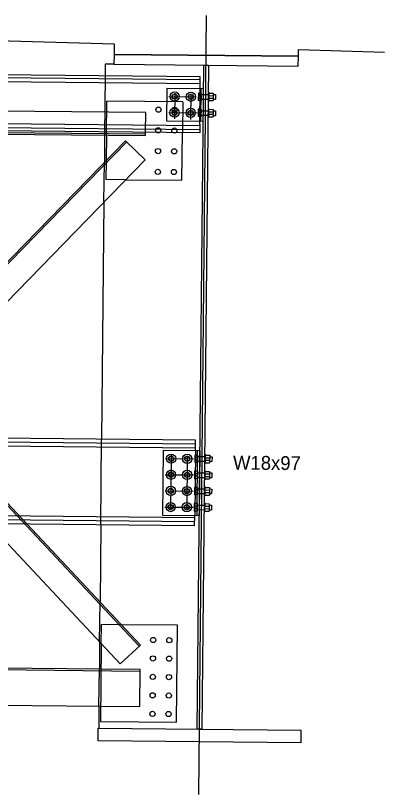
# Model space of a CAD drawing. Extents: x 632312 to 632425, y 378332 to 378413.
# Drawn here: x 632348.57 to 632355.24, y 378382.52 to 378396.59 of the extents above; entities that cross this region are included whole.
import ezdxf

# ---------------------------------------------------------------- set-up
doc = ezdxf.new("R2010")
doc.units = 0
for name, color, linetype in [('B_Boring', 7, 'Continuous'), ('B_Boring Annot', 7, 'Continuous'), ('R_Proposed Const Limits Cut', 7, 'Continuous'), ('R_Shade Removal', 7, 'Continuous'), ('R_Wall', 7, 'Continuous'), ('SHT_Dimensions', 7, 'Continuous')]:
    doc.layers.add(name, color=color, linetype=linetype)

msp = doc.modelspace()

# ---------------------------------------------------------------- linework, layer by layer
at = {"layer": 'B_Boring'}
for p, q in [((632350.191, 378395.714), (632350.189, 378395.499)), ((632350.347, 378395.712), (632350.191, 378395.714)), ((632351.908, 378395.482), (632340.867, 378395.592)), ((632351.907, 378395.432), (632340.866, 378395.541)), ((632351.906, 378395.294), (632351.908, 378395.482)), ((632351.301, 378395.275), (632351.296, 378394.692)), ((632351.968, 378395.269), (632351.301, 378395.275)), ((632351.874, 378395.192), (632351.872, 378395.056)), ((632351.925, 378395.146), (632351.873, 378395.147)), ((632351.926, 378395.191), (632351.874, 378395.192)), ((632351.921, 378394.686), (632351.926, 378395.269)), ((632351.926, 378395.191), (632351.924, 378395.056)), ((632352.051, 378395.206), (632352.049, 378395.039)), ((632352.051, 378395.206), (632352.061, 378395.205)), ((632352.061, 378395.205), (632352.06, 378395.039)), ((632352.061, 378395.19), (632352.144, 378395.189)), ((632352.061, 378395.145), (632352.144, 378395.144)), ((632352.144, 378395.189), (632352.143, 378395.054)), ((632352.144, 378395.163), (632352.186, 378395.163)), ((632352.186, 378395.163), (632352.185, 378395.079)), ((632350.216, 378395.047), (632350.216, 378395.047)), ((632351.924, 378395.056), (632351.872, 378395.056)), ((632351.925, 378395.101), (632351.873, 378395.101)), ((632352.049, 378395.039), (632352.06, 378395.039)), ((632352.06, 378395.1), (632352.144, 378395.099)), ((632352.06, 378395.054), (632352.143, 378395.054)), ((632352.143, 378395.08), (632352.185, 378395.079)), ((632351.871, 378394.9), (632351.869, 378394.765)), ((632351.922, 378394.854), (632351.87, 378394.855)), ((632351.923, 378394.899), (632351.871, 378394.9)), ((632351.923, 378394.899), (632351.921, 378394.764)), ((632352.048, 378394.914), (632352.046, 378394.747)), ((632352.048, 378394.914), (632352.058, 378394.914)), ((632352.058, 378394.914), (632352.057, 378394.747)), ((632352.058, 378394.898), (632352.142, 378394.897)), ((632352.058, 378394.853), (632352.141, 378394.852)), ((632352.142, 378394.897), (632352.14, 378394.762)), ((632352.141, 378394.871), (632352.183, 378394.871)), ((632352.183, 378394.871), (632352.182, 378394.788)), ((632351.921, 378394.764), (632351.869, 378394.765)), ((632351.922, 378394.809), (632351.87, 378394.81)), ((632352.046, 378394.747), (632352.057, 378394.747)), ((632352.057, 378394.808), (632352.141, 378394.807)), ((632352.057, 378394.763), (632352.14, 378394.762)), ((632352.14, 378394.788), (632352.182, 378394.788)), ((632351.898, 378394.524), (632340.857, 378394.634)), ((632351.898, 378394.474), (632340.857, 378394.583)), ((632351.296, 378394.692), (632351.962, 378394.686)), ((632351.899, 378394.627), (632351.898, 378394.474)), ((632346.377, 378394.468), (632350.918, 378394.423)), ((632350.178, 378394.43), (632350.174, 378393.94)), ((632350.918, 378394.423), (632350.919, 378394.483)), ((632351.577, 378393.616), (632351.585, 378394.477)), ((632350.567, 378393.626), (632351.577, 378393.616)), ((632350.166, 378393.217), (632350.124, 378388.936)), ((632351.821, 378388.847), (632340.821, 378388.956)), ((632351.822, 378388.92), (632340.822, 378389.029)), ((632351.82, 378388.728), (632351.822, 378388.92)), ((632351.236, 378388.734), (632351.225, 378387.567)), ((632351.903, 378388.727), (632351.236, 378388.734)), ((632351.85, 378387.561), (632351.861, 378388.727)), ((632351.986, 378388.664), (632351.996, 378388.664)), ((632351.996, 378388.664), (632351.995, 378388.497)), ((632351.809, 378388.65), (632351.807, 378388.514)), ((632351.86, 378388.604), (632351.808, 378388.605)), ((632351.86, 378388.559), (632351.808, 378388.56)), ((632351.861, 378388.649), (632351.809, 378388.65)), ((632351.995, 378388.558), (632352.078, 378388.557)), ((632351.996, 378388.648), (632352.079, 378388.647)), ((632351.996, 378388.603), (632352.079, 378388.602)), ((632352.079, 378388.647), (632352.078, 378388.512)), ((632352.078, 378388.538), (632352.12, 378388.537)), ((632352.079, 378388.621), (632352.121, 378388.621)), ((632352.121, 378388.621), (632352.12, 378388.537)), ((632351.859, 378388.514), (632351.807, 378388.514)), ((632351.984, 378388.497), (632351.995, 378388.497)), ((632351.995, 378388.513), (632352.078, 378388.512)), ((632351.806, 378388.358), (632351.804, 378388.223)), ((632351.857, 378388.313), (632351.805, 378388.313)), ((632351.857, 378388.267), (632351.805, 378388.268)), ((632351.858, 378388.358), (632351.806, 378388.358)), ((632351.983, 378388.372), (632351.993, 378388.372)), ((632351.993, 378388.372), (632351.992, 378388.205)), ((632351.992, 378388.266), (632352.076, 378388.265)), ((632351.993, 378388.356), (632352.076, 378388.355)), ((632351.993, 378388.311), (632352.076, 378388.31)), ((632352.076, 378388.355), (632352.075, 378388.22)), ((632352.075, 378388.246), (632352.117, 378388.246)), ((632352.076, 378388.329), (632352.118, 378388.329)), ((632352.118, 378388.329), (632352.117, 378388.246)), ((632351.856, 378388.222), (632351.804, 378388.223)), ((632351.981, 378388.205), (632351.992, 378388.205)), ((632351.992, 378388.221), (632352.075, 378388.22)), ((632351.803, 378388.067), (632351.801, 378387.931)), ((632351.854, 378388.021), (632351.802, 378388.021)), ((632351.854, 378387.976), (632351.802, 378387.976)), ((632351.855, 378388.066), (632351.803, 378388.067)), ((632351.98, 378388.08), (632351.99, 378388.08)), ((632351.99, 378388.08), (632351.989, 378387.914)), ((632351.989, 378387.974), (632352.073, 378387.974)), ((632351.99, 378388.065), (632352.074, 378388.064)), ((632351.99, 378388.02), (632352.073, 378388.019)), ((632352.074, 378388.064), (632352.072, 378387.928)), ((632352.073, 378388.038), (632352.115, 378388.037)), ((632352.115, 378388.037), (632352.114, 378387.954)), ((632351.853, 378387.931), (632351.801, 378387.931)), ((632351.978, 378387.914), (632351.989, 378387.914)), ((632351.989, 378387.929), (632352.072, 378387.928)), ((632352.072, 378387.954), (632352.114, 378387.954)), ((632351.8, 378387.775), (632351.799, 378387.639)), ((632351.851, 378387.729), (632351.799, 378387.73)), ((632351.851, 378387.684), (632351.799, 378387.685)), ((632351.852, 378387.774), (632351.8, 378387.775)), ((632351.977, 378387.789), (632351.988, 378387.789)), ((632351.988, 378387.789), (632351.986, 378387.622)), ((632351.986, 378387.683), (632352.07, 378387.682)), ((632351.987, 378387.773), (632352.071, 378387.772)), ((632351.987, 378387.728), (632352.07, 378387.727)), ((632352.071, 378387.772), (632352.069, 378387.637)), ((632352.07, 378387.746), (632352.112, 378387.746)), ((632352.112, 378387.746), (632352.111, 378387.662)), ((632351.807, 378387.442), (632340.808, 378387.551)), ((632351.225, 378387.567), (632351.891, 378387.56)), ((632351.851, 378387.639), (632351.799, 378387.639)), ((632351.806, 378387.37), (632351.808, 378387.561)), ((632351.975, 378387.622), (632351.986, 378387.622)), ((632351.986, 378387.638), (632352.069, 378387.637)), ((632352.07, 378387.663), (632352.111, 378387.662)), ((632351.806, 378387.37), (632340.807, 378387.479)), ((632350.108, 378387.386), (632350.095, 378385.998)), ((632350.087, 378385.275), (632350.083, 378384.782)), ((632350.826, 378385.218), (632350.462, 378384.876)), ((632350.114, 378384.781), (632346.281, 378384.819)), ((632346.274, 378384.153), (632350.107, 378384.115)), ((632350.076, 378384.115), (632350.072, 378383.714))]:
    msp.add_line(p, q, dxfattribs=at)
for points in [[(632353.681, 378395.679), (632353.682, 378395.856), (632350.349, 378395.889), (632350.347, 378395.712)], [(632351.936, 378383.696), (632351.853, 378383.697), (632351.972, 378395.696), (632352.056, 378395.695)], [(632353.728, 378383.678), (632353.726, 378383.449), (632350.059, 378383.485), (632350.061, 378383.714)]]:
    msp.add_lwpolyline(points, close=True, dxfattribs=at)
for points in [[(632350.21, 378394.43), (632350.205, 378393.972)], [(632347.136, 378390.114), (632350.914, 378393.982), (632350.556, 378394.331), (632347.131, 378390.825)], [(632350.462, 378384.876), (632348.087, 378387.407)], [(632348.779, 378387.4), (632350.826, 378385.218)], [(632350.118, 378385.242), (632350.104, 378383.839), (632350.104, 378383.839), (632350.104, 378383.839), (632351.479, 378383.825), (632351.497, 378385.575), (632350.482, 378385.585)]]:
    msp.add_lwpolyline(points, dxfattribs=at)
for centre in [(632351.446, 378395.128), (632351.738, 378395.125), (632351.152, 378394.892), (632351.443, 378394.837), (632351.443, 378394.889), (632351.735, 378394.834), (632351.148, 378394.517), (632351.44, 378394.514), (632351.144, 378394.142), (632351.436, 378394.139), (632351.141, 378393.767), (632351.432, 378393.764), (632351.381, 378388.586), (632351.672, 378388.583), (632351.378, 378388.295), (632351.67, 378388.292), (632351.375, 378388.003), (632351.667, 378388), (632351.372, 378387.711), (632351.664, 378387.709), (632351.057, 378385.309), (632351.348, 378385.306), (632351.053, 378384.975), (632351.345, 378384.972), (632351.05, 378384.642), (632351.342, 378384.639), (632351.047, 378384.309), (632351.338, 378384.306), (632351.043, 378383.975), (632351.335, 378383.973)]:
    msp.add_circle(centre, 0.0469, dxfattribs=at)
at = {"layer": 'B_Boring Annot'}
for p, q in [((632346.394, 378396.197), (632350.351, 378396.079)), ((632350.351, 378396.079), (632350.349, 378395.889)), ((632353.682, 378395.856), (632353.684, 378395.979)), ((632353.684, 378395.979), (632355.238, 378395.932)), ((632350.349, 378395.889), (632353.682, 378395.856))]:
    msp.add_line(p, q, dxfattribs=at)
at = {"layer": 'R_Proposed Const Limits Cut'}
for p, q in [((632351.906, 378395.357), (632340.865, 378395.467)), ((632350.189, 378395.499), (632350.178, 378394.43)), ((632351.899, 378394.627), (632351.906, 378395.294)), ((632351.925, 378395.165), (632352.05, 378395.164)), ((632350.21, 378394.43), (632350.216, 378395.047)), ((632351.591, 378395.033), (632350.216, 378395.047)), ((632351.591, 378395.033), (632351.585, 378394.477)), ((632351.925, 378395.082), (632352.05, 378395.081)), ((632350.922, 378394.84), (632341.839, 378394.93)), ((632351.923, 378394.873), (632352.048, 378394.872)), ((632350.919, 378394.483), (632350.922, 378394.84)), ((632351.922, 378394.79), (632352.047, 378394.789)), ((632351.899, 378394.599), (632340.858, 378394.708)), ((632350.918, 378394.449), (632341.835, 378394.539)), ((632350.578, 378394.309), (632341.766, 378385.287)), ((632342.173, 378394.393), (632350.804, 378385.197)), ((632350.166, 378393.217), (632350.174, 378393.94)), ((632350.205, 378393.972), (632350.202, 378393.63)), ((632350.567, 378393.626), (632350.202, 378393.63)), ((632347.31, 378388.964), (632348.779, 378387.4)), ((632351.82, 378388.774), (632340.821, 378388.883)), ((632350.108, 378387.386), (632350.124, 378388.936)), ((632351.82, 378388.728), (632351.808, 378387.561)), ((632351.86, 378388.623), (632351.985, 378388.622)), ((632351.86, 378388.54), (632351.985, 378388.539)), ((632351.857, 378388.332), (632351.982, 378388.33)), ((632351.857, 378388.248), (632351.982, 378388.247)), ((632351.854, 378387.957), (632351.979, 378387.955)), ((632351.855, 378388.04), (632351.98, 378388.039)), ((632351.852, 378387.748), (632351.977, 378387.747)), ((632351.808, 378387.515), (632340.808, 378387.625)), ((632351.851, 378387.665), (632351.976, 378387.664)), ((632350.087, 378385.275), (632350.095, 378385.998)), ((632350.118, 378385.242), (632350.122, 378385.589)), ((632350.482, 378385.585), (632350.122, 378385.589)), ((632350.822, 378384.743), (632341.739, 378384.833)), ((632350.076, 378384.115), (632350.083, 378384.782)), ((632350.822, 378384.774), (632350.114, 378384.781)), ((632350.815, 378384.108), (632350.822, 378384.774)), ((632350.107, 378384.115), (632350.815, 378384.108))]:
    msp.add_line(p, q, dxfattribs=at)
for centre, radius in [((632351.446, 378395.128), 0.0833), ((632351.446, 378395.128), 0.0417), ((632351.738, 378395.125), 0.0833), ((632351.738, 378395.125), 0.0417), ((632351.443, 378394.837), 0.0833), ((632351.443, 378394.837), 0.0417), ((632351.735, 378394.834), 0.0833), ((632351.735, 378394.834), 0.0417), ((632351.381, 378388.586), 0.0833), ((632351.672, 378388.583), 0.0833), ((632351.381, 378388.586), 0.0417), ((632351.672, 378388.583), 0.0417), ((632351.378, 378388.295), 0.0833), ((632351.378, 378388.295), 0.0417), ((632351.67, 378388.292), 0.0833), ((632351.67, 378388.292), 0.0417), ((632351.375, 378388.003), 0.0833), ((632351.375, 378388.003), 0.0417), ((632351.667, 378388), 0.0833), ((632351.667, 378388), 0.0417), ((632351.372, 378387.711), 0.0833), ((632351.372, 378387.711), 0.0417), ((632351.664, 378387.709), 0.0833), ((632351.664, 378387.709), 0.0417)]:
    msp.add_circle(centre, radius, dxfattribs=at)
at = {"layer": 'R_Shade Removal'}
msp.add_line((632351.883, 378382.519), (632352.023, 378396.591), dxfattribs=at)
at = {"layer": 'R_Wall'}
for p, q in [((632351.446, 378395.189), (632351.442, 378394.724)), ((632351.738, 378395.179), (632351.733, 378394.716)), ((632351.342, 378395.129), (632351.836, 378395.124)), ((632351.339, 378394.838), (632351.849, 378394.833)), ((632351.277, 378388.587), (632351.786, 378388.582)), ((632351.381, 378388.647), (632351.372, 378387.654)), ((632351.673, 378388.638), (632351.663, 378387.652)), ((632351.274, 378388.296), (632351.784, 378388.291)), ((632351.271, 378388.004), (632351.781, 378387.999)), ((632351.268, 378387.712), (632351.778, 378387.707))]:
    msp.add_line(p, q, dxfattribs=at)
at = {"layer": 'SHT_Dimensions'}
for p, q in [((632351.903, 378388.727), (632351.891, 378387.56)), ((632351.381, 378388.647), (632351.375, 378387.957)), ((632351.861, 378388.649), (632351.859, 378388.514)), ((632351.858, 378388.358), (632351.856, 378388.222)), ((632351.855, 378388.066), (632351.853, 378387.931)), ((632351.98, 378388.08), (632351.978, 378387.914)), ((632351.852, 378387.774), (632351.851, 378387.639))]:
    msp.add_line(p, q, dxfattribs=at)

# ---------------------------------------------------------------- texts
msp.add_text('W18x97', height=0.25, rotation=359.4304, dxfattribs=at).set_placement((632352.499, 378388.39))

doc.saveas('drawing.dxf')
